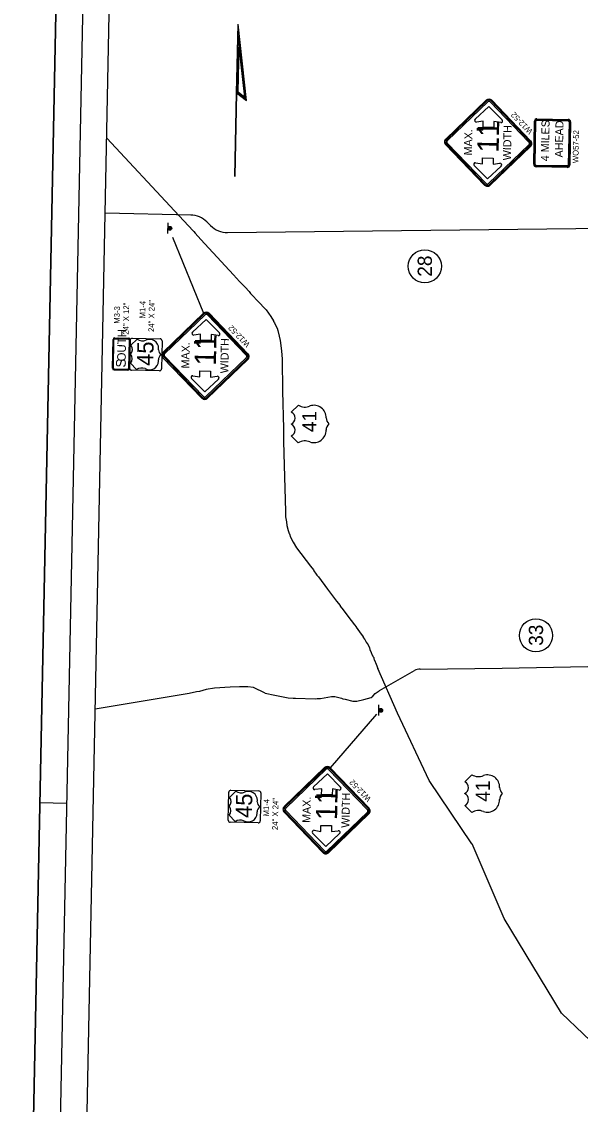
# Model space of a CAD drawing. Extents: x 2191881 to 2513407, y 347956 to 627029.
# Drawn here: x 2411346 to 2458451, y 488157 to 579445 of the extents above; entities that cross this region are included whole.
import ezdxf

# ---------------------------------------------------------------- set-up
doc = ezdxf.new("R2010")
doc.units = 0
for name, color, linetype in [('Level 52', 7, 'Continuous'), ('P_MISC', 7, 'Continuous'), ('P_RDWY_Text', 7, 'Continuous'), ('P_SGN_Cell', 7, 'Continuous'), ('P_TC', 7, 'Continuous'), ('PLT_Sheet_Border', 7, 'Continuous')]:
    doc.layers.add(name, color=color, linetype=linetype)

msp = doc.modelspace()

# ---------------------------------------------------------------- linework, layer by layer
at = {"layer": 'Level 52'}
for p, q in [((2415960, 442501), (2418814, 584223)), ((2412846, 511360), (2412936, 515859)), ((2412891, 513609), (2415141, 513564))]:
    msp.add_line(p, q, dxfattribs=at)
at = {"layer": 'P_MISC'}
for p, q in [((2429473, 573454), (2429589, 579238)), ((2430317, 572794), (2429589, 579238)), ((2429538, 573485), (2429634, 578269)), ((2430236, 572939), (2429634, 578269)), ((2429603, 573516), (2429679, 577299)), ((2430155, 573084), (2429679, 577299)), ((2429330, 566384), (2429473, 573454)), ((2429352, 566384), (2429494, 573437)), ((2429473, 573454), (2430317, 572794)), ((2429538, 573485), (2430236, 572939)), ((2429603, 573516), (2430155, 573084))]:
    msp.add_line(p, q, dxfattribs=at)
msp.add_lwpolyline([(2429590, 579232), (2429589, 579232)], dxfattribs=at)
at = {"layer": 'P_RDWY_Text'}
for p, q in [((2425597, 563142), (2418392, 563287)), ((2427280, 562249), (2426969, 562559)), ((2428714, 561665), (2468331, 562111)), ((2424071, 561268), (2426677, 554862)), ((2445335, 558817), (2445335, 558817)), ((2434083, 546516), (2434681, 547114)), ((2435494, 545561), (2435494, 545561)), ((2434075, 544529), (2434672, 543931)), ((2454708, 527698), (2454708, 527698)), ((2441386, 524913), (2441386, 524913)), ((2443023, 521152), (2441386, 524911)), ((2444948, 524855), (2451851, 524932)), ((2451851, 524932), (2466668, 525217)), ((2441518, 523049), (2444465, 524724)), ((2441255, 521042), (2437366, 516536)), ((2445714, 515453), (2443023, 521152)), ((2448709, 515355), (2449306, 515953)), ((2449316, 510128), (2445714, 515452)), ((2450119, 514400), (2450119, 514400)), ((2448700, 513368), (2449297, 512770)), ((2452036, 503824), (2449317, 510128)), ((2456867, 495857), (2452036, 503824)), ((2465460, 487557), (2456867, 495857))]:
    msp.add_line(p, q, dxfattribs=at)
msp.add_lwpolyline([(2411346, 436901), (2414427, 589870), (2513407, 587876), (2510326, 434907)], close=True, dxfattribs=at)
for points in [[(2418520, 569618), (2424242, 563503), (2425796, 561819), (2425857, 561763)], [(2425857, 561763), (2425962, 561613), (2426454, 561085), (2428510, 558859), (2429212, 558092), (2429726, 557526), (2430192, 557055), (2430516, 556682), (2430649, 556535), (2430809, 556364), (2431240, 555910), (2431949, 555136), (2432357, 554586), (2432580, 554218), (2432581, 554173), (2432663, 554054), (2432906, 553520), (2432907, 553480), (2432948, 553412), (2433056, 552928), (2433152, 552560), (2433261, 551681), (2433301, 550982)], [(2433301, 550974), (2433331, 548297), (2433417, 545144), (2433429, 544043), (2433485, 542058), (2433579, 538156), (2433600, 537690), (2433663, 537259), (2433715, 536951), (2433818, 536537), (2433892, 536291), (2433924, 536260), (2434020, 535967), (2434225, 535546), (2434522, 535072), (2435686, 533535), (2435945, 533214), (2435980, 533129), (2436180, 532870), (2436228, 532778), (2436362, 532631), (2437139, 531601), (2437883, 530596), (2438191, 530225), (2438208, 530158), (2438451, 529861), (2438937, 529205), (2439122, 528951), (2439409, 528589), (2439536, 528421), (2439537, 528390), (2439844, 528008), (2440139, 527564), (2440139, 527532), (2440270, 527342), (2440388, 527112), (2440549, 526889), (2440671, 526654), (2440689, 526520), (2440819, 526261), (2440896, 526039), (2440951, 525986), (2440951, 525931), (2441036, 525821), (2441037, 525716), (2441066, 525660), (2441143, 525461), (2441181, 525423), (2441225, 525276), (2441386, 524913)], [(2431890, 522833), (2430884, 523291), (2430421, 523350), (2429705, 523364), (2428917, 523335), (2427592, 523238), (2426909, 523136), (2426354, 522971), (2426091, 522937), (2425472, 522793), (2417550, 521478)], [(2431890, 522833), (2432685, 522651), (2433821, 522432), (2434231, 522404), (2434422, 522406), (2436099, 522360), (2436266, 522362), (2436541, 522366), (2437465, 522544), (2437757, 522531), (2438317, 522405), (2438418, 522356), (2438627, 522308), (2439271, 522158), (2439596, 522162), (2440187, 522295), (2440827, 522469), (2440959, 522571), (2441148, 522798), (2441231, 522866), (2441495, 523036), (2441518, 523049)]]:
    msp.add_lwpolyline(points, dxfattribs=at)
for centre in [(2445335, 558817), (2454708, 527698)]:
    msp.add_circle(centre, 1398, dxfattribs=at)
for centre, radius, start, end in [((2425557, 561142), 2000, 45.08737, 88.84622), ((2428692, 563665), 2000, 225.08737, 270.64431), ((2435237, 547980), 1030, 237.31366, 294.1957), ((2435991, 546066), 1030, 357.80954, 108.90524), ((2433852, 546019), 548, 293.11923, 65.07067), ((2437776, 546064), 755, 181.24325, 225.27704), ((2433852, 545011), 548, 294.92933, 66.88077), ((2435982, 544979), 1030, 251.09476, 2.19046), ((2437767, 544982), 755, 133.77282, 178.75675), ((2435228, 543065), 1030, 65.8043, 122.68634), ((2441386, 524912), 1, 89.34437, 203.53177), ((2451851, 524933), 1, 270.63683, 271.10097), ((2444960, 523855), 1000, 90.63683, 119.62034), ((2445693, 524864), 1, 269.34437, 270.63683), ((2443024, 521152), 1, 203.53177, 205.27492), ((2449862, 516819), 1030, 237.31366, 294.1957), ((2450617, 514905), 1030, 357.80954, 108.90524), ((2445715, 515453), 1, 205.27492, 214.08485), ((2448478, 514858), 548, 293.11923, 65.07067), ((2452401, 514903), 755, 181.24325, 225.27704), ((2448478, 513850), 548, 294.92933, 66.88077), ((2452392, 513821), 755, 133.77282, 178.75675), ((2450608, 513818), 1030, 251.09476, 2.19046), ((2449853, 511904), 1030, 65.8043, 122.68634), ((2449316, 510128), 1, 23.33117, 34.08485), ((2452037, 503824), 1, 203.33117, 211.23363), ((2456867, 495858), 1, 211.23363, 225.991)]:
    msp.add_arc(centre, radius, start, end, dxfattribs=at)
at = {"layer": 'P_SGN_Cell'}
for p, q in [((2449582, 571219), (2450742, 572290)), ((2450742, 572290), (2451858, 571173)), ((2450268, 571043), (2449694, 570976)), ((2450257, 570542), (2450267, 571043)), ((2451167, 571025), (2451156, 570524)), ((2451736, 570935), (2451166, 571025)), ((2451156, 570524), (2450257, 570542)), ((2450194, 567454), (2450205, 567955)), ((2450205, 567955), (2451104, 567937)), ((2451104, 567937), (2451094, 567436)), ((2450619, 566188), (2449503, 567305)), ((2449624, 567543), (2450195, 567454)), ((2451779, 567259), (2450619, 566188)), ((2451093, 567435), (2451667, 567502)), ((2450619, 566188), (2450619, 566188)), ((2425747, 553258), (2426907, 554328)), ((2426907, 554329), (2428023, 553212)), ((2419002, 550219), (2419051, 552650)), ((2419036, 550220), (2419085, 552649)), ((2419081, 550219), (2419130, 552648)), ((2419187, 552704), (2420357, 552680)), ((2419188, 552749), (2420358, 552725)), ((2419189, 552782), (2420358, 552759)), ((2420412, 552623), (2420363, 550193)), ((2420457, 552622), (2420408, 550192)), ((2420491, 552621), (2420442, 550191)), ((2420442, 550225), (2420490, 552587)), ((2421091, 552680), (2420544, 552155)), ((2420662, 552753), (2423024, 552705)), ((2423189, 552533), (2423166, 551352)), ((2423189, 552533), (2423189, 552533)), ((2426433, 553081), (2425858, 553015)), ((2426422, 552580), (2426432, 553081)), ((2427321, 552562), (2426422, 552580)), ((2427331, 553063), (2427321, 552562)), ((2427901, 552974), (2427330, 553063)), ((2422895, 551786), (2422897, 551893)), ((2420514, 550655), (2421039, 550109)), ((2422875, 550822), (2422877, 550929)), ((2423166, 551352), (2423142, 550171)), ((2419134, 550083), (2420304, 550059)), ((2419135, 550117), (2420305, 550093)), ((2419136, 550162), (2420306, 550138)), ((2422970, 550006), (2420608, 550053)), ((2425789, 549582), (2426360, 549492)), ((2426359, 549492), (2426369, 549993)), ((2426369, 549993), (2427269, 549975)), ((2427269, 549975), (2427259, 549474)), ((2426784, 548227), (2425668, 549343)), ((2427944, 549297), (2426784, 548227)), ((2427258, 549474), (2427832, 549540)), ((2426784, 548227), (2426784, 548227)), ((2435960, 514940), (2437120, 516011)), ((2437120, 516011), (2438236, 514894)), ((2428764, 512107), (2428811, 514469)), ((2429412, 514562), (2428865, 514037)), ((2428983, 514635), (2431345, 514587)), ((2431511, 514415), (2431487, 513234)), ((2431510, 514415), (2431511, 514415)), ((2436646, 514764), (2436071, 514697)), ((2436634, 514263), (2436645, 514764)), ((2437534, 514245), (2436634, 514263)), ((2437544, 514746), (2437534, 514245)), ((2438114, 514656), (2437543, 514746)), ((2431216, 513668), (2431218, 513775)), ((2431487, 513234), (2431463, 512053)), ((2428835, 512537), (2429360, 511991)), ((2431196, 512704), (2431198, 512811)), ((2431291, 511888), (2428929, 511935)), ((2436002, 511264), (2436573, 511175)), ((2436572, 511175), (2436582, 511676)), ((2436582, 511676), (2437482, 511658)), ((2437471, 511156), (2438045, 511223)), ((2437482, 511658), (2437472, 511157)), ((2436997, 509909), (2435881, 511026)), ((2438157, 510980), (2436997, 509909)), ((2436997, 509909), (2436997, 509909))]:
    msp.add_line(p, q, dxfattribs=at)
for points in [[(2450512, 572823), (2447105, 569550)], [(2450572, 572761), (2447164, 569488)], [(2450646, 572684), (2447238, 569411)], [(2454121, 569275), (2450849, 572682)], [(2454198, 569349), (2450926, 572756)], [(2454260, 569409), (2450988, 572815)], [(2454519, 567415), (2454592, 571065)], [(2454572, 567412), (2454645, 571066)], [(2454637, 567411), (2454711, 571065)], [(2454791, 571208), (2457435, 571155)], [(2454792, 571142), (2457433, 571089)], [(2454794, 571261), (2457436, 571208)], [(2457511, 571008), (2457437, 567355)], [(2457577, 571006), (2457503, 567355)], [(2457629, 571006), (2457556, 567352)], [(2447095, 569073), (2450368, 565665)], [(2447157, 569132), (2450430, 565725)], [(2447234, 569206), (2450507, 565799)], [(2450712, 565795), (2454119, 569068)], [(2450786, 565717), (2454194, 568990)], [(2450845, 565656), (2454253, 568929)], [(2457354, 567159), (2454713, 567212)], [(2457355, 567211), (2454714, 567264)], [(2457356, 567277), (2454715, 567330)], [(2426677, 554862), (2423269, 551588)], [(2426736, 554800), (2423329, 551527)], [(2426811, 554723), (2423403, 551449)], [(2430286, 551313), (2427014, 554720)], [(2430363, 551388), (2427091, 554794)], [(2430425, 551447), (2427153, 554854)], [(2423260, 551111), (2426533, 547704)], [(2423322, 551171), (2426595, 547763)], [(2423399, 551245), (2426672, 547837)], [(2426876, 547833), (2430284, 551106)], [(2426951, 547756), (2430358, 551029)], [(2427010, 547694), (2430418, 550967)], [(2436890, 516544), (2433482, 513271)], [(2436949, 516482), (2433542, 513209)], [(2437024, 516405), (2433616, 513132)], [(2440498, 512996), (2437227, 516403)], [(2440576, 513070), (2437304, 516477)], [(2440638, 513130), (2437366, 516536)], [(2433473, 512794), (2436746, 509386)], [(2433534, 512853), (2436808, 509446)], [(2433612, 512927), (2436885, 509520)], [(2437089, 509516), (2440497, 512789)], [(2437164, 509438), (2440571, 512712)], [(2437223, 509377), (2440631, 512650)]]:
    msp.add_lwpolyline(points, dxfattribs=at)
for centre, radius, start, end in [((2450746, 572580), 337, 43.84622, 133.84622), ((2450746, 572580), 252, 43.84622, 133.84622), ((2450746, 572580), 145, 43.84622, 133.84622), ((2449677, 571116), 141, 132.70164, 276.60197), ((2451758, 571074), 141, 261.07912, 44.97866), ((2454790, 571063), 198, 88.84622, 179.40173), ((2454790, 571063), 145, 89.52254, 178.84622), ((2454790, 571063), 79.1, 88.35811, 178.84622), ((2457432, 571010), 79.1, 358.84622, 88.84622), ((2457432, 571010), 145, 358.27931, 88.84622), ((2457432, 571010), 198, 358.84622, 88.84622), ((2447338, 569307), 337, 133.84433, 223.84622), ((2447338, 569307), 252, 133.84433, 223.84622), ((2447338, 569307), 145, 133.84433, 223.84622), ((2454019, 569172), 145, 313.85344, 44.49709), ((2454019, 569172), 252, 313.85344, 44.49709), ((2454019, 569172), 337, 313.85344, 44.49709), ((2449603, 567404), 141, 81.09048, 224.99081), ((2451684, 567362), 141, 312.71379, 96.61332), ((2454717, 567409), 198, 178.29072, 268.84622), ((2454717, 567409), 145, 178.84622, 268.84622), ((2454717, 567409), 79.1, 178.84622, 268.84622), ((2457358, 567356), 198, 268.84622, 358.84622), ((2457358, 567356), 145, 268.84622, 359.41314), ((2457358, 567356), 79.1, 268.84622, 358.84622), ((2450611, 565899), 337, 223.84622, 313.84622), ((2450611, 565899), 252, 223.84622, 313.84622), ((2450611, 565899), 145, 223.84622, 313.84622), ((2426911, 554618), 337, 43.84622, 133.84622), ((2426911, 554618), 252, 43.84622, 133.84622), ((2426911, 554618), 145, 43.84622, 133.84622), ((2425842, 553154), 141, 132.70164, 276.60197), ((2427923, 553112), 141, 261.07912, 44.97866), ((2419186, 552647), 135, 88.84622, 178.84622), ((2419186, 552647), 101, 88.84622, 178.84622), ((2419186, 552647), 56.2, 88.84622, 178.84622), ((2420356, 552624), 56.2, 358.84622, 88.84622), ((2420356, 552624), 135, 358.84622, 88.84622), ((2420356, 552624), 101, 358.84622, 88.84622), ((2420659, 552584), 169, 88.84622, 178.84622), ((2421541, 553280), 750, 233.11428, 291.9873), ((2422147, 551908), 750, 358.84616, 115.69277), ((2423021, 552536), 169, 358.84622, 88.84622), ((2420139, 551038), 536, 314.41906, 43.27339), ((2420154, 551788), 536, 314.41906, 43.27339), ((2423437, 551778), 542, 179.18852, 231.63404), ((2423503, 551345), 337, 133.84433, 223.84622), ((2423503, 551345), 252, 133.84433, 223.84622), ((2423503, 551345), 145, 133.84433, 223.84622), ((2430184, 551211), 252, 313.85344, 44.49709), ((2430184, 551211), 337, 313.85344, 44.49709), ((2422125, 550837), 750, 240.09813, 358.84629), ((2423419, 550915), 542, 126.05841, 178.50393), ((2430184, 551211), 145, 313.85344, 44.49709), ((2419137, 550218), 135, 179.61188, 268.84622), ((2419137, 550218), 101, 178.84622, 268.84622), ((2419137, 550218), 56.2, 178.84622, 268.84622), ((2420307, 550194), 135, 268.84622, 358.84622), ((2420307, 550194), 101, 268.84622, 358.84622), ((2420307, 550194), 56.2, 268.84622, 358.84622), ((2420611, 550222), 169, 178.84622, 268.84622), ((2421467, 549493), 750, 67.71592, 124.79823), ((2422973, 550174), 169, 268.84622, 358.84622), ((2425768, 549443), 141, 81.09048, 224.99081), ((2427848, 549401), 141, 312.71379, 96.61332), ((2426776, 547937), 252, 223.84622, 313.84622), ((2426776, 547937), 145, 223.84622, 313.84622), ((2426776, 547937), 337, 223.84622, 313.84622), ((2437124, 516301), 337, 43.84622, 133.84622), ((2437124, 516301), 252, 43.84622, 133.84622), ((2437124, 516301), 145, 43.84622, 133.84622), ((2436055, 514837), 141, 132.70164, 276.60197), ((2438136, 514795), 141, 261.07912, 44.97866), ((2428980, 514466), 169, 88.84622, 178.84622), ((2428475, 513670), 536, 314.41906, 43.27339), ((2429862, 515162), 750, 233.11428, 291.9873), ((2430468, 513790), 750, 358.84616, 115.69277), ((2431342, 514418), 169, 358.84622, 88.84622), ((2428460, 512920), 536, 314.41906, 43.27339), ((2431741, 512797), 542, 126.05841, 178.50393), ((2431758, 513660), 542, 179.18852, 231.63404), ((2433716, 513028), 337, 133.84433, 223.84622), ((2433716, 513028), 252, 133.84433, 223.84622), ((2433716, 513028), 145, 133.84433, 223.84622), ((2440397, 512893), 252, 313.85344, 44.49709), ((2440397, 512893), 337, 313.85344, 44.49709), ((2430446, 512719), 750, 240.09813, 358.84629), ((2440397, 512893), 145, 313.85344, 44.49709), ((2428932, 512104), 169, 178.84622, 268.84622), ((2429788, 511375), 750, 67.71592, 124.79823), ((2431294, 512056), 169, 268.84622, 358.84622), ((2435980, 511125), 141, 81.09048, 224.99081), ((2438061, 511083), 141, 312.71379, 96.61332), ((2436989, 509620), 252, 223.84622, 313.84622), ((2436989, 509620), 145, 223.84622, 313.84622), ((2436989, 509620), 337, 223.84622, 313.84622)]:
    msp.add_arc(centre, radius, start, end, dxfattribs=at)
at = {"layer": 'P_TC'}
for p, q in [((2423681, 561574), (2423693, 562474)), ((2441459, 520930), (2441470, 521830))]:
    msp.add_line(p, q, dxfattribs=at)
for centre, radius in [((2423845, 562020), 158), ((2423845, 562020), 90), ((2423845, 562020), 22.5), ((2441622, 521375), 158), ((2441622, 521375), 90), ((2441622, 521375), 22.5)]:
    msp.add_circle(centre, radius, dxfattribs=at)
at = {"layer": 'PLT_Sheet_Border'}
for points in [[(2510326, 434907), (2513407, 587876), (2414427, 589870), (2411346, 436901)], [(2508098, 436032), (2511097, 584952), (2416617, 586855), (2413617, 437935)]]:
    msp.add_lwpolyline(points, close=True, dxfattribs=at)

# ---------------------------------------------------------------- texts
at = {"layer": 'P_RDWY_Text'}
for s, p in [('28', (2445935, 557938)), ('41', (2436200, 544834)), ('33', (2455308, 526819)), ('41', (2450825, 513672))]:
    msp.add_text(s, height=1200, rotation=90, dxfattribs=at).set_placement(p)
at = {"layer": 'P_SGN_Cell'}
for s, height, rotation, p in [('W12-52', 486, 133.84622, (2454474, 570235)), ('11', 1800, 88.84622, (2451562, 568381)), ('WIDTH', 675, 88.84622, (2452598, 567748)), ('4 MILES', 675, 88.84622, (2455789, 567672)), ('AHEAD', 675, 88.84622, (2456972, 567989)), ('MAX.', 675, 88.84622, (2449307, 568161)), ("'", 1800, 88.84622, (2451497, 570096)), ('WO57-52', 486, 88.84622, (2458286, 567511)), ('24" X 24"', 486, 88.84622, (2422510, 553274)), ('M3-3', 486, 88.84622, (2419609, 553969)), ('24" X 12"', 486, 88.84622, (2420362, 553048)), ('M1-4', 486, 88.84622, (2421761, 554416)), ('OUTH', 720, 88.84622, (2420116, 550791)), ('W12-52', 486, 133.84622, (2430639, 552274)), ('45', 1380, 88.84622, (2422440, 550411)), ('MAX.', 675, 88.84622, (2425472, 550199)), ("'", 1800, 88.84622, (2427662, 552135)), ('11', 1800, 88.84622, (2427726, 550420)), ('WIDTH', 675, 88.84622, (2428763, 549787)), ('S', 823, 88.84622, (2420116, 550273)), ('W12-52', 486, 133.84622, (2440852, 513956)), ('45', 1380, 88.84622, (2430761, 512293)), ('24" X 24"', 486, 88.84622, (2432945, 511282)), ('MAX.', 675, 88.84622, (2435685, 511882)), ("'", 1800, 88.84622, (2437875, 513817)), ('11', 1800, 88.84622, (2437939, 512102)), ('WIDTH', 675, 88.84622, (2438976, 511469)), ('M1-4', 486, 88.84622, (2432197, 512424))]:
    msp.add_text(s, height=height, rotation=rotation, dxfattribs=at).set_placement(p)

doc.saveas('drawing.dxf')
